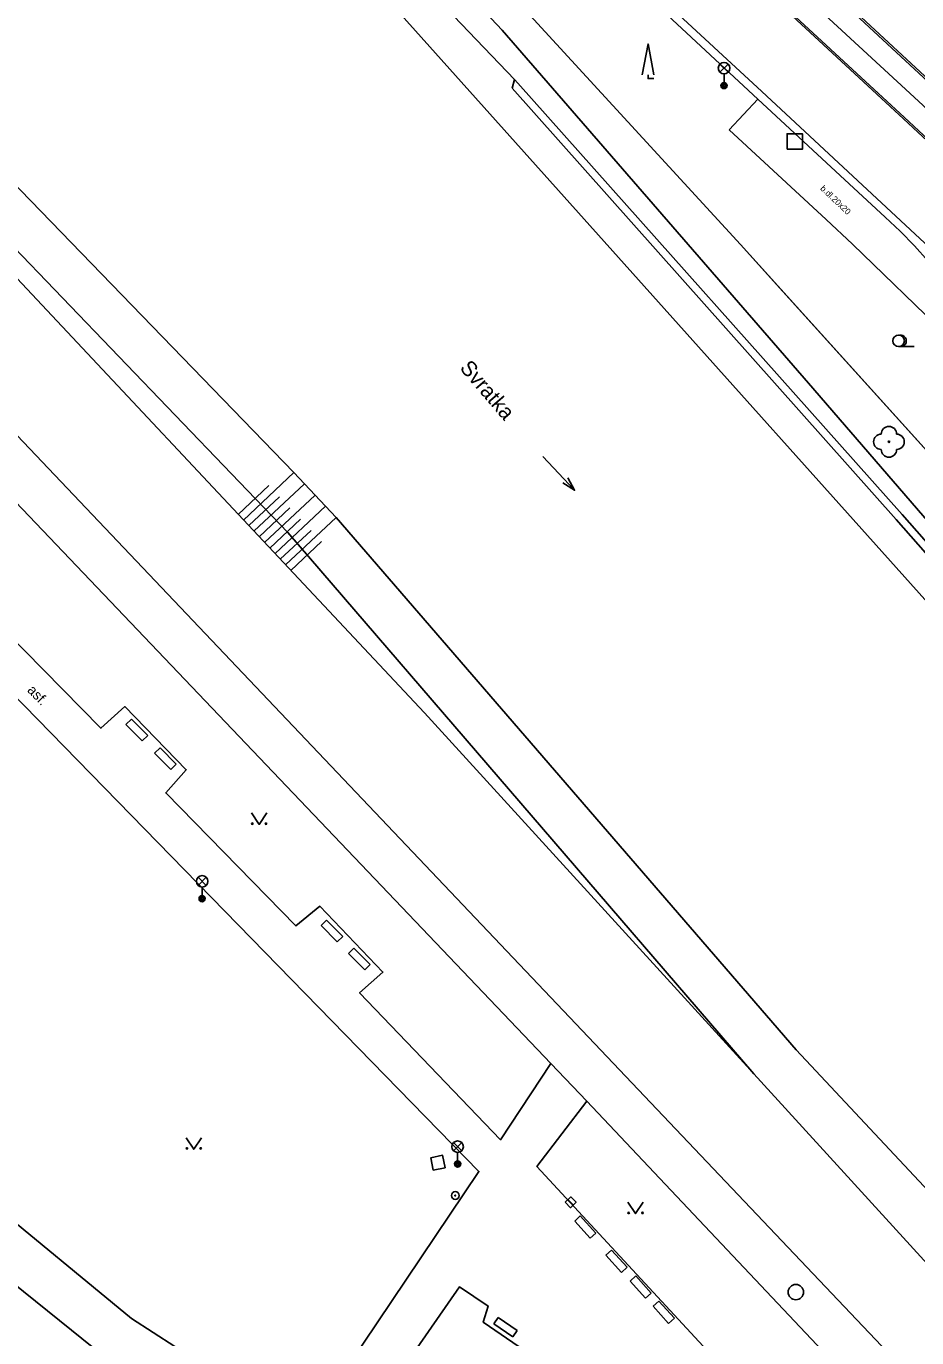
# Model space of a CAD drawing. Extents: x -598932 to -598196, y -1162207 to -1161504.
# Drawn here: x -598839 to -598781.1, y -1161884.4 to -1161799.2 of the extents above; entities that cross this region are included whole.
import ezdxf

# ---------------------------------------------------------------- set-up
doc = ezdxf.new("R2010")
doc.units = 0
for name, color, linetype in [('Level 22', 7, 'Continuous'), ('Level 25', 7, 'Continuous'), ('Level 26', 7, 'Continuous'), ('Level 27', 7, 'Continuous'), ('Level 33', 7, 'Continuous'), ('Level 36', 7, 'Continuous'), ('Level 45', 7, 'Continuous'), ('specificka linie pasportu komunikaci', 7, 'Continuous'), ('TM - CD - osa koleji', 7, 'Continuous'), ('TM - chodniky - VP', 7, 'Continuous'), ('TM - hladina vodniho toku_ bazenu_ nadrze', 7, 'Continuous'), ('TM - horni hrana svahu', 7, 'Continuous'), ('TM - komunikace - VP', 7, 'Continuous'), ('TM - letecke snimky - pomocna linie', 7, 'Continuous'), ('TM - pomocna konstrukcna linie', 7, 'Continuous'), ('TM - popis povrchu', 7, 'Continuous'), ('TM - popis vodnich toku a nadrzi', 7, 'Continuous'), ('TM - rozhrani mezi zpev. plochami mezi sebou - VP', 7, 'Continuous'), ('TM - rozhrani ploch obecne - VP', 7, 'Continuous'), ('TM - srafovani', 7, 'Continuous'), ('TM - zabradli - VP', 7, 'Continuous'), ('TM - zed operna - VP', 7, 'Continuous')]:
    doc.layers.add(name, color=color, linetype=linetype)

msp = doc.modelspace()

# ---------------------------------------------------------------- linework, layer by layer
at = {"layer": 'Level 22'}
msp.add_circle((-598782.91, -1161826.17), 0.05, dxfattribs=at)
for centre, start, end in [((-598783.41, -1161826.17), 90, 270), ((-598782.91, -1161825.67), 0, 180), ((-598782.41, -1161826.17), 270, 90), ((-598782.91, -1161826.67), 180, 0)]:
    msp.add_arc(centre, 0.5, start, end, dxfattribs=at)
at = {"layer": 'Level 25'}
for radius in [0.25, 0.0303]:
    msp.add_circle((-598811.1, -1161875.17), radius, dxfattribs=at)
at = {"layer": 'Level 26'}
msp.add_lwpolyline([(-598789.53, -1161807.15), (-598788.53, -1161807.15), (-598788.53, -1161806.15), (-598789.53, -1161806.15)], close=True, dxfattribs=at)
at = {"layer": 'Level 27'}
msp.add_line((-598803.776, -1161875.432), (-598803.424, -1161875.788), dxfattribs=at)
msp.add_lwpolyline([(-598803.954, -1161875.608), (-598803.602, -1161875.964), (-598803.246, -1161875.612), (-598803.598, -1161875.256)], close=True, dxfattribs=at)
msp.add_circle((-598788.96, -1161881.45), 0.5, dxfattribs=at)
at = {"layer": 'Level 33'}
for p, q in [((-598793.895, -1161802.15), (-598793.365, -1161801.62)), ((-598793.895, -1161801.62), (-598793.365, -1161802.15)), ((-598793.63, -1161802.26), (-598793.63, -1161803.01)), ((-598827.825, -1161855.01), (-598827.295, -1161854.48)), ((-598827.825, -1161854.48), (-598827.295, -1161855.01)), ((-598827.56, -1161855.12), (-598827.56, -1161855.87)), ((-598811.215, -1161872.26), (-598810.685, -1161871.73)), ((-598811.215, -1161871.73), (-598810.685, -1161872.26)), ((-598810.95, -1161872.37), (-598810.95, -1161873.12))]:
    msp.add_line(p, q, dxfattribs=at)
for centre, radius in [((-598793.63, -1161801.885), 0.375), ((-598793.63, -1161803.01), 0.2), ((-598793.63, -1161803.01), 0.145), ((-598793.63, -1161803.01), 0.0876), ((-598827.56, -1161854.745), 0.375), ((-598827.56, -1161855.87), 0.2), ((-598827.56, -1161855.87), 0.145), ((-598827.56, -1161855.87), 0.0876), ((-598810.95, -1161871.995), 0.375), ((-598810.95, -1161873.12), 0.2), ((-598810.95, -1161873.12), 0.145), ((-598810.95, -1161873.12), 0.0876)]:
    msp.add_circle(centre, radius, dxfattribs=at)
at = {"layer": 'Level 36'}
msp.add_line((-598782.28, -1161819.985), (-598781.28, -1161819.985), dxfattribs=at)
for points in [[(-598798.945, -1161802.31), (-598798.57, -1161800.31), (-598798.195, -1161802.31)], [(-598798.57, -1161802.31), (-598798.57, -1161802.56), (-598798.195, -1161802.56)], [(-598824.35, -1161850.3), (-598823.85, -1161851.05), (-598823.35, -1161850.3)], [(-598828.6, -1161871.41), (-598828.1, -1161872.16), (-598827.6, -1161871.41)], [(-598799.88, -1161875.6), (-598799.38, -1161876.35), (-598798.88, -1161875.6)]]:
    msp.add_lwpolyline(points, dxfattribs=at)
for centre, radius in [((-598782.28, -1161819.61), 0.375), ((-598824.3, -1161851), 0.05), ((-598823.401, -1161851), 0.05), ((-598828.55, -1161872.11), 0.05), ((-598827.651, -1161872.11), 0.05), ((-598799.83, -1161876.3), 0.05), ((-598798.931, -1161876.3), 0.05)]:
    msp.add_circle(centre, radius, dxfattribs=at)
msp.add_arc((-598782.155, -1161819.61), 0.375, 260.40593, 99.59407, dxfattribs=at)
at = {"layer": 'Level 45'}
msp.add_line((-598805.402, -1161827.132), (-598803.35, -1161829.32), dxfattribs=at)
msp.add_lwpolyline([(-598803.781, -1161828.524), (-598803.35, -1161829.32), (-598804.117, -1161828.838)], dxfattribs=at)
at = {"layer": 'specificka linie pasportu komunikaci'}
msp.add_lwpolyline([(-598804.9, -1161866.58), (-598802.56, -1161869.04)], dxfattribs=at)
at = {"layer": 'TM - CD - osa koleji'}
msp.add_lwpolyline([(-598823.67, -1161764.63), (-598809.08, -1161778.04), (-598795.12, -1161790.98), (-598780.98, -1161804.03), (-598752.01, -1161830.97), (-598740.39, -1161841.76), (-598737.43, -1161844.53), (-598720.51, -1161860.13)], dxfattribs=at)
at = {"layer": 'TM - chodniky - VP'}
for points in [[(-598880.74, -1161784.6), (-598866.42, -1161797.65), (-598860.43, -1161803.84), (-598803.26, -1161864)], [(-598793.3, -1161805.9), (-598791.43, -1161803.89)], [(-598793.3, -1161805.9), (-598786.99, -1161811.73), (-598785.27, -1161813.32), (-598773.11, -1161825.11)], [(-598804.9, -1161866.58), (-598808.16, -1161871.55), (-598817.32, -1161861.99), (-598815.81, -1161860.64), (-598819.91, -1161856.37), (-598821.46, -1161857.64), (-598829.93, -1161849), (-598828.59, -1161847.49), (-598832.58, -1161843.39), (-598834.14, -1161844.79), (-598842.84, -1161835.97), (-598841.33, -1161834.48), (-598845.52, -1161830.23), (-598846.96, -1161831.61), (-598855.66, -1161822.89), (-598854.19, -1161821.34), (-598858.23, -1161817.26), (-598859.73, -1161818.65), (-598866.13, -1161812.23), (-598861.29, -1161807.42), (-598804.9, -1161866.58)], [(-598867.84, -1161813.9), (-598809.56, -1161873.6), (-598820.89, -1161890.44), (-598832.15, -1161883.16), (-598841.68, -1161875.32), (-598851.13, -1161866.08), (-598878.95, -1161836.17), (-598885.26, -1161828.7), (-598885.4, -1161826.42), (-598876.78, -1161822.62), (-598867.84, -1161813.9)], [(-598803.26, -1161864), (-598777.69, -1161890.94), (-598758.15, -1161912.24), (-598742.93, -1161928.84)], [(-598802.56, -1161869.04), (-598805.79, -1161873.29), (-598792.28, -1161887.88), (-598796.19, -1161892.37), (-598809.28, -1161883.41), (-598808.97, -1161882.36), (-598810.82, -1161881.1), (-598818.34, -1161891.95)], [(-598748.5, -1161928.1), (-598760.28, -1161914.27), (-598779.92, -1161893), (-598802.56, -1161869.04)], [(-598833.04, -1161886.35), (-598842.98, -1161878.35)]]:
    msp.add_lwpolyline(points, dxfattribs=at)
at = {"layer": 'TM - hladina vodniho toku_ bazenu_ nadrze'}
for points in [[(-598720.27, -1161904.76), (-598749.26, -1161871.38), (-598790.83, -1161824.98), (-598815.91, -1161796.95), (-598834.93, -1161777.35), (-598836.37, -1161776.01), (-598850.71, -1161762.63), (-598866.62, -1161749.21), (-598892.99, -1161728.98)], [(-598847.28, -1161801.66), (-598821.59, -1161828.17), (-598818.85, -1161831.09)], [(-598818.85, -1161831.09), (-598788.93, -1161865.71), (-598745.82, -1161911.74), (-598735.06, -1161923.85)]]:
    msp.add_lwpolyline(points, dxfattribs=at)
at = {"layer": 'TM - horni hrana svahu'}
for points in [[(-598932.017, -1161697.604), (-598929.76, -1161698.95), (-598888.91, -1161727.38), (-598861.19, -1161748.52), (-598845.68, -1161761.08), (-598825.16, -1161781.28), (-598808.06, -1161799.42), (-598788.14, -1161822.37), (-598765.72, -1161848.31), (-598730.99, -1161888.48), (-598729.85, -1161889.88)], [(-598737.74, -1161926.39), (-598791.69, -1161867.26), (-598813.1, -1161843.8), (-598846.83, -1161807.87), (-598870.15, -1161785.99), (-598909.01, -1161754.64), (-598931.6, -1161739.49), (-598932.017, -1161739.209)], [(-598792.56, -1161813.35), (-598806.23, -1161798.45)], [(-598792.56, -1161813.35), (-598790.41, -1161815.73), (-598774.14, -1161833.73), (-598756.14, -1161854.37), (-598747.26, -1161864.54)]]:
    msp.add_lwpolyline(points, dxfattribs=at)
at = {"layer": 'TM - komunikace - VP'}
for points in [[(-598791.43, -1161803.89), (-598807.19, -1161789.23)], [(-598783.15, -1161811.56), (-598786.08, -1161808.86), (-598791.43, -1161803.89)], [(-598783.15, -1161811.56), (-598782.18, -1161812.48), (-598781.25, -1161813.44), (-598780.35, -1161814.43)]]:
    msp.add_lwpolyline(points, dxfattribs=at)
at = {"layer": 'TM - letecke snimky - pomocna linie'}
for points in [[(-598932.017, -1161736.019), (-598925.65, -1161740.07), (-598887.55, -1161768.09), (-598865.96, -1161786.27), (-598821.99, -1161832.07), (-598791.69, -1161867.26)], [(-598832, -1161776.77), (-598807.26, -1161802.61)]]:
    msp.add_lwpolyline(points, dxfattribs=at)
at = {"layer": 'TM - pomocna konstrukcna linie'}
msp.add_lwpolyline([(-598807.4, -1161803.19), (-598807.26, -1161802.61)], dxfattribs=at)
at = {"layer": 'TM - rozhrani mezi zpev. plochami mezi sebou - VP'}
for points in [[(-598758.89, -1161822.69), (-598765.45, -1161816.6), (-598780.07, -1161803.03), (-598794.2, -1161789.91), (-598802.31, -1161782.41)], [(-598802.2, -1161782.35), (-598794.12, -1161789.83), (-598779.99, -1161802.95), (-598765.37, -1161816.52), (-598758.81, -1161822.61)], [(-598804.39, -1161784.4), (-598802.91, -1161785.78), (-598796.12, -1161792.07), (-598781.97, -1161805.17)], [(-598804.38, -1161784.26), (-598796.05, -1161791.99), (-598781.9, -1161805.09)], [(-598806.77, -1161788.96), (-598791.18, -1161803.4), (-598770.01, -1161823.1), (-598754.95, -1161837.06)], [(-598781.9, -1161805.09), (-598767.4, -1161818.57)]]:
    msp.add_lwpolyline(points, dxfattribs=at)
at = {"layer": 'TM - rozhrani ploch obecne - VP'}
for points in [[(-598807.26, -1161802.61), (-598807.04, -1161802.85), (-598782.06, -1161830.89)], [(-598781.97, -1161805.17), (-598767.47, -1161818.65)], [(-598782.06, -1161830.89), (-598746.93, -1161870.82)], [(-598832.51, -1161844.56), (-598832.15, -1161844.2)], [(-598831.45, -1161845.62), (-598832.51, -1161844.56)], [(-598832.15, -1161844.2), (-598831.1, -1161845.27)], [(-598831.1, -1161845.27), (-598831.45, -1161845.62)], [(-598830.65, -1161846.42), (-598830.29, -1161846.06)], [(-598829.59, -1161847.48), (-598830.65, -1161846.42)], [(-598830.29, -1161846.06), (-598829.24, -1161847.13)], [(-598829.24, -1161847.13), (-598829.59, -1161847.48)], [(-598819.83, -1161857.62), (-598819.48, -1161857.27)], [(-598819.48, -1161857.27), (-598818.42, -1161858.33)], [(-598818.77, -1161858.68), (-598819.83, -1161857.62)], [(-598818.42, -1161858.33), (-598818.77, -1161858.68)], [(-598818.04, -1161859.44), (-598817.69, -1161859.08)], [(-598817.69, -1161859.08), (-598816.64, -1161860.15)], [(-598816.99, -1161860.5), (-598818.04, -1161859.44)], [(-598816.64, -1161860.15), (-598816.99, -1161860.5)], [(-598812.54, -1161873.53), (-598812.7, -1161872.73), (-598811.93, -1161872.55), (-598811.76, -1161873.37), (-598812.54, -1161873.53)], [(-598803.34, -1161876.84), (-598802.98, -1161876.5)], [(-598802.34, -1161877.95), (-598803.34, -1161876.84)], [(-598802.98, -1161876.5), (-598801.97, -1161877.61)], [(-598801.97, -1161877.61), (-598802.34, -1161877.95)], [(-598801.31, -1161879.05), (-598800.94, -1161878.72)], [(-598800.94, -1161878.72), (-598799.93, -1161879.83)], [(-598800.3, -1161880.17), (-598801.31, -1161879.05)], [(-598799.93, -1161879.83), (-598800.3, -1161880.17)], [(-598799.74, -1161880.73), (-598799.37, -1161880.4)], [(-598799.37, -1161880.4), (-598798.36, -1161881.51)], [(-598798.73, -1161881.85), (-598799.74, -1161880.73)], [(-598798.36, -1161881.51), (-598798.73, -1161881.85)], [(-598798.24, -1161882.36), (-598797.87, -1161882.03)], [(-598797.87, -1161882.03), (-598796.86, -1161883.14)], [(-598808.6, -1161883.52), (-598808.32, -1161883.11)], [(-598808.32, -1161883.11), (-598807.08, -1161883.95)], [(-598797.23, -1161883.48), (-598798.24, -1161882.36)], [(-598796.86, -1161883.14), (-598797.23, -1161883.48)], [(-598807.37, -1161884.36), (-598808.6, -1161883.52)], [(-598807.08, -1161883.95), (-598807.37, -1161884.36)]]:
    msp.add_lwpolyline(points, dxfattribs=at)
at = {"layer": 'TM - srafovani'}
for points in [[(-598821.59, -1161828.17), (-598824.87, -1161831.26)], [(-598823.22, -1161829.01), (-598825.22, -1161830.89)], [(-598820.9, -1161828.9), (-598824.19, -1161831.99)], [(-598822.53, -1161829.74), (-598824.53, -1161831.62)], [(-598820.22, -1161829.63), (-598823.5, -1161832.71)], [(-598821.85, -1161830.47), (-598823.85, -1161832.35)], [(-598819.53, -1161830.36), (-598822.82, -1161833.44)], [(-598818.85, -1161831.09), (-598822.14, -1161834.17)], [(-598821.16, -1161831.2), (-598823.16, -1161833.08)], [(-598820.48, -1161831.93), (-598822.48, -1161833.81)], [(-598819.79, -1161832.66), (-598821.79, -1161834.54)]]:
    msp.add_lwpolyline(points, dxfattribs=at)
at = {"layer": 'TM - zabradli - VP'}
for points in [[(-598792.56, -1161813.35), (-598806.23, -1161798.45)], [(-598792.56, -1161813.35), (-598774.14, -1161833.73), (-598747.26, -1161864.54)]]:
    msp.add_lwpolyline(points, dxfattribs=at)
at = {"layer": 'TM - zed operna - VP'}
msp.add_lwpolyline([(-598807.4, -1161803.19), (-598782.43, -1161831.22), (-598747.29, -1161871.17)], dxfattribs=at)

# ---------------------------------------------------------------- texts
at = {"layer": 'TM - popis povrchu'}
for s, height, rotation, p in [('b.dl.20x20', 0.4, 316.63112, (-598787.41, -1161809.75)), ('asf.', 0.65, 314.31, (-598838.97, -1161842.36))]:
    msp.add_text(s, height=height, rotation=rotation, dxfattribs=at).set_placement(p)
at = {"layer": 'TM - popis vodnich toku a nadrzi'}
msp.add_text('Svratka', height=1, rotation=310.62, dxfattribs=at).set_placement((-598810.86, -1161821.4))

doc.saveas('drawing.dxf')
